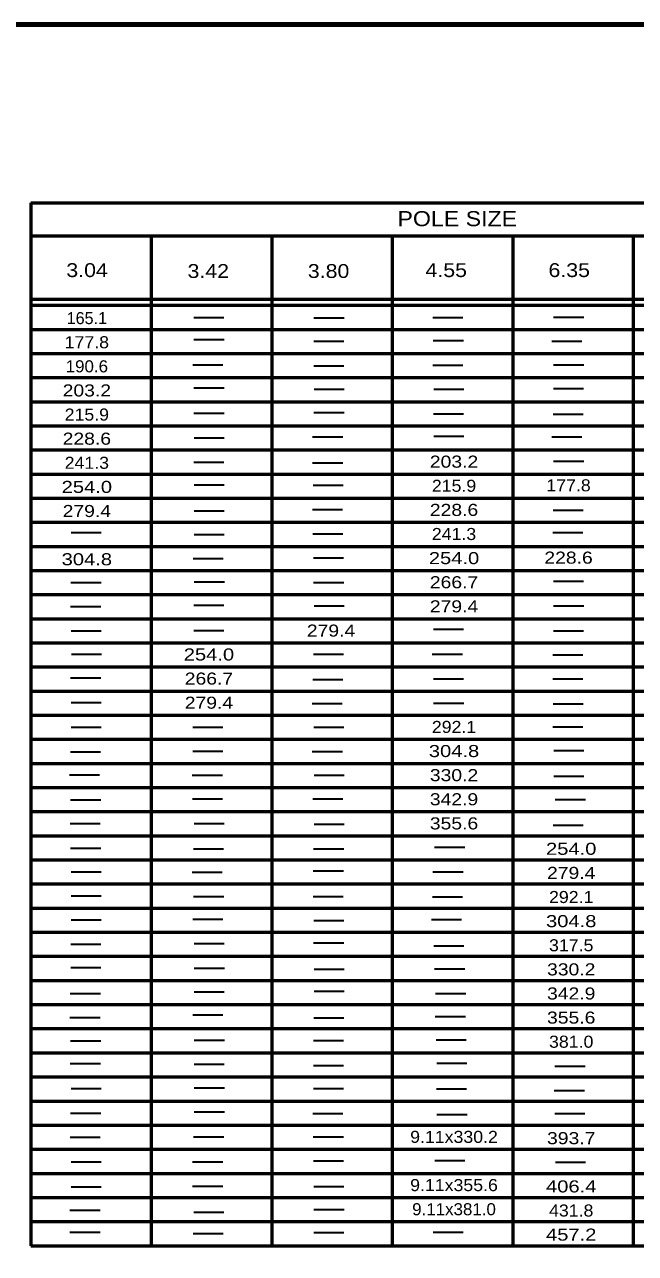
# Model space of a CAD drawing. Extents: x -711 to 145, y 25 to 569.
# Drawn here: x -252.6 to -112, y 280.2 to 562.7 of the extents above; entities that cross this region are included whole.
import ezdxf
from ezdxf.enums import TextEntityAlignment as Align

# ---------------------------------------------------------------- set-up
doc = ezdxf.new("R2010")
doc.units = 0
doc.header["$LTSCALE"] = 1.1
doc.layers.add('1', color=7, linetype='Continuous', lineweight=53)

msp = doc.modelspace()

# ---------------------------------------------------------------- linework, layer by layer
at = {"layer": '1'}
for p, q in [((-251.147, 521.717), (-251.147, 281.939)), ((-251.147, 521.717), (-44.796, 521.717)), ((-251.147, 514.094), (-57.107, 514.094)), ((-223.427, 514.094), (-223.427, 281.939)), ((-195.707, 514.094), (-195.707, 281.939)), ((-167.987, 514.094), (-167.987, 513.999)), ((-167.987, 514.094), (-167.987, 281.939)), ((-140.267, 514.094), (-140.267, 281.939)), ((-112.547, 514.094), (-112.547, 513.999)), ((-112.547, 514.094), (-112.547, 281.939)), ((-251.147, 499.541), (109.194, 499.541)), ((-251.147, 498.155), (109.194, 498.155)), ((-251.147, 492.611), (109.194, 492.611)), ((-251.147, 487.067), (109.194, 487.067)), ((-251.147, 481.523), (109.194, 481.523)), ((-251.147, 475.979), (109.194, 475.979)), ((-251.147, 470.435), (109.194, 470.435)), ((-251.147, 464.891), (109.194, 464.891)), ((-251.147, 459.347), (109.194, 459.347)), ((-251.147, 453.803), (109.194, 453.803)), ((-251.147, 448.259), (109.194, 448.259)), ((-251.147, 442.715), (109.194, 442.715)), ((-251.147, 437.171), (109.194, 437.171)), ((-251.147, 431.627), (109.194, 431.627)), ((-251.147, 426.083), (109.194, 426.083)), ((-251.147, 420.539), (109.194, 420.539)), ((-251.147, 414.995), (109.194, 414.995)), ((-251.147, 409.451), (109.194, 409.451)), ((-251.147, 403.907), (109.194, 403.907)), ((-251.147, 398.363), (109.194, 398.363)), ((-251.147, 392.819), (109.194, 392.819)), ((-251.147, 387.275), (109.194, 387.275)), ((-251.147, 381.731), (109.194, 381.731)), ((-251.147, 376.187), (109.194, 376.187)), ((-251.147, 370.643), (109.194, 370.643)), ((-251.147, 365.099), (109.194, 365.099)), ((-251.147, 359.555), (109.194, 359.555)), ((-251.147, 354.011), (109.194, 354.011)), ((-251.147, 348.467), (109.194, 348.467)), ((-251.147, 342.923), (109.194, 342.923)), ((-251.147, 337.379), (109.194, 337.379)), ((-251.147, 331.835), (109.194, 331.835)), ((-251.147, 326.291), (109.194, 326.291)), ((-251.147, 320.747), (109.194, 320.747)), ((-251.147, 315.203), (109.194, 315.203)), ((-251.147, 309.659), (109.194, 309.659)), ((-251.147, 304.115), (109.194, 304.115)), ((-251.147, 298.571), (109.194, 298.571)), ((-251.147, 293.027), (109.194, 293.027)), ((-251.147, 287.483), (109.194, 287.483)), ((-251.147, 281.939), (109.213, 281.939))]:
    msp.add_line(p, q, dxfattribs=at)
at = {"layer": '1', "lineweight": 35}
for p, q in [((-213.641, 495.341), (-206.71, 495.341)), ((-185.997, 495.27), (-179.067, 495.27)), ((-158.633, 495.341), (-151.703, 495.341)), ((-130.847, 495.413), (-123.917, 495.413)), ((-213.607, 490.263), (-206.677, 490.263)), ((-186.035, 489.91), (-179.105, 489.91)), ((-158.527, 490.015), (-151.597, 490.015)), ((-131.268, 489.913), (-124.338, 489.913)), ((-213.855, 484.444), (-206.925, 484.444)), ((-186.035, 484.234), (-179.105, 484.234)), ((-158.633, 484.339), (-151.703, 484.339)), ((-130.847, 484.482), (-123.917, 484.482)), ((-213.607, 479.156), (-206.677, 479.156)), ((-185.964, 478.874), (-179.034, 478.874)), ((-158.422, 478.874), (-151.492, 478.874)), ((-130.88, 478.979), (-123.95, 478.979)), ((-213.607, 473.337), (-206.677, 473.337)), ((-185.997, 473.514), (-179.067, 473.514)), ((-158.493, 473.16), (-151.563, 473.16)), ((-130.986, 473.126), (-124.056, 473.126)), ((-213.573, 467.695), (-206.643, 467.695)), ((-186.313, 467.871), (-179.383, 467.871)), ((-158.422, 468.082), (-151.492, 468.082)), ((-131.268, 467.871), (-124.338, 467.871)), ((-213.644, 462.052), (-206.714, 462.052)), ((-186.313, 461.947), (-179.383, 461.947)), ((-130.843, 462.334), (-123.913, 462.334)), ((-213.573, 456.869), (-206.643, 456.869)), ((-186.208, 456.764), (-179.278, 456.764)), ((-213.573, 450.873), (-206.643, 450.873)), ((-186.351, 451.193), (-179.421, 451.193)), ((-130.982, 451.05), (-124.052, 451.05)), ((-241.886, 445.867), (-234.956, 445.867)), ((-213.573, 445.408), (-206.643, 445.408)), ((-186.28, 445.585), (-179.35, 445.585)), ((-131.053, 445.867), (-124.123, 445.867)), ((-213.784, 439.942), (-206.853, 439.942)), ((-186.103, 440.048), (-179.173, 440.048)), ((-241.923, 434.406), (-234.993, 434.406)), ((-213.535, 434.582), (-206.605, 434.582)), ((-186.069, 434.439), (-179.139, 434.439)), ((-130.877, 434.688), (-123.947, 434.688)), ((-241.994, 428.869), (-235.064, 428.869)), ((-213.644, 429.222), (-206.714, 429.222)), ((-185.963, 429.046), (-179.033, 429.046)), ((-130.843, 429.046), (-123.913, 429.046)), ((-241.855, 423.332), (-234.925, 423.332)), ((-213.644, 423.403), (-206.714, 423.403)), ((-158.49, 423.685), (-151.56, 423.685)), ((-130.88, 423.332), (-123.95, 423.332)), ((-241.784, 417.904), (-234.854, 417.904)), ((-186.103, 417.938), (-179.173, 417.938)), ((-158.772, 417.904), (-151.842, 417.904)), ((-131.057, 417.761), (-124.127, 417.761)), ((-241.994, 412.472), (-235.064, 412.472)), ((-186.242, 412.119), (-179.312, 412.119)), ((-158.49, 412.224), (-151.56, 412.224)), ((-131.057, 412.296), (-124.127, 412.296)), ((-241.889, 406.83), (-234.959, 406.83)), ((-186.419, 406.582), (-179.489, 406.582)), ((-158.456, 406.687), (-151.526, 406.687)), ((-130.952, 406.477), (-124.022, 406.477)), ((-131.057, 401.222), (-124.127, 401.222)), ((-241.889, 401.117), (-234.959, 401.117)), ((-213.855, 401.117), (-206.925, 401.117)), ((-186.031, 401.117), (-179.101, 401.117)), ((-213.892, 395.651), (-206.962, 395.651)), ((-186.385, 395.579), (-179.455, 395.579)), ((-130.809, 395.794), (-123.879, 395.794)), ((-242.032, 395.474), (-235.102, 395.474)), ((-242.28, 390.186), (-235.35, 390.186)), ((-213.998, 390.114), (-207.068, 390.114)), ((-185.96, 390.08), (-179.03, 390.08)), ((-130.811, 389.853), (-123.881, 389.853)), ((-241.998, 384.472), (-235.068, 384.472)), ((-213.93, 384.649), (-207, 384.649)), ((-186.246, 384.649), (-179.316, 384.649)), ((-130.459, 384.528), (-123.529, 384.528)), ((-242.103, 379.006), (-235.173, 379.006)), ((-213.576, 379.007), (-206.646, 379.007)), ((-185.963, 378.864), (-179.033, 378.864)), ((-130.984, 378.599), (-124.054, 378.599)), ((-241.998, 373.364), (-235.068, 373.364)), ((-213.719, 373.188), (-206.789, 373.188)), ((-186.069, 373.188), (-179.139, 373.188)), ((-158.24, 373.575), (-151.31, 373.575)), ((-241.893, 367.899), (-234.963, 367.899)), ((-214.035, 367.794), (-207.105, 367.794)), ((-186.14, 368.147), (-179.21, 368.147)), ((-158.624, 367.903), (-151.694, 367.903)), ((-241.855, 362.396), (-234.925, 362.396)), ((-213.682, 362.253), (-206.752, 362.253)), ((-186.212, 362.257), (-179.282, 362.257)), ((-158.729, 362.116), (-151.799, 362.116)), ((-241.855, 356.825), (-234.925, 356.825)), ((-213.858, 357.002), (-206.928, 357.002)), ((-186.035, 356.682), (-179.105, 356.682)), ((-158.979, 356.894), (-152.049, 356.894)), ((-241.961, 351.288), (-235.031, 351.288)), ((-213.576, 351.394), (-206.646, 351.394)), ((-186.069, 351.571), (-179.139, 351.571)), ((-158.413, 350.904), (-151.483, 350.904)), ((-241.961, 345.928), (-235.031, 345.928)), ((-213.543, 345.718), (-206.613, 345.718)), ((-185.963, 345.541), (-179.033, 345.541)), ((-158.236, 345.578), (-151.306, 345.578)), ((-242.066, 339.899), (-235.136, 339.899)), ((-213.577, 340.286), (-206.647, 340.286)), ((-185.963, 340.463), (-179.033, 340.463)), ((-157.991, 339.948), (-151.061, 339.948)), ((-242.137, 334.396), (-235.207, 334.396)), ((-213.862, 334.997), (-206.932, 334.997)), ((-186.035, 334.362), (-179.105, 334.362)), ((-158.064, 334.625), (-151.134, 334.625)), ((-241.994, 329.002), (-235.064, 329.002)), ((-213.543, 329.178), (-206.613, 329.178)), ((-186.103, 329.107), (-179.173, 329.107)), ((-157.889, 329.3), (-150.96, 329.3)), ((-242.066, 323.856), (-235.136, 323.856)), ((-213.573, 323.641), (-206.643, 323.641)), ((-186.103, 323.393), (-179.173, 323.393)), ((-157.715, 323.895), (-150.785, 323.895)), ((-130.527, 323.228), (-123.597, 323.228)), ((-241.889, 318.071), (-234.959, 318.071)), ((-213.535, 318.248), (-206.605, 318.248)), ((-186.103, 318.071), (-179.173, 318.071)), ((-157.82, 318.006), (-150.89, 318.006)), ((-130.705, 317.586), (-123.775, 317.586)), ((-241.995, 312.429), (-235.065, 312.429)), ((-213.535, 312.711), (-206.605, 312.711)), ((-186.28, 312.357), (-179.35, 312.357)), ((-157.679, 312.119), (-150.749, 312.119)), ((-130.564, 312.365), (-123.634, 312.365)), ((-242.1, 306.892), (-235.17, 306.892)), ((-213.674, 306.963), (-206.744, 306.963)), ((-186.137, 306.963), (-179.207, 306.963)), ((-241.889, 301.249), (-234.959, 301.249)), ((-213.923, 301.249), (-206.993, 301.249)), ((-186.103, 301.426), (-179.173, 301.426)), ((-158.175, 301.503), (-151.245, 301.503)), ((-130.412, 301.175), (-123.482, 301.175)), ((-241.889, 295.464), (-234.959, 295.464)), ((-213.923, 295.607), (-206.993, 295.607)), ((-186.031, 295.536), (-179.101, 295.536)), ((-242.137, 290.142), (-235.207, 290.142)), ((-213.64, 289.683), (-206.71, 289.683)), ((-185.997, 290.247), (-179.067, 290.247)), ((-242.137, 285.064), (-235.207, 285.064)), ((-213.783, 284.71), (-206.853, 284.71)), ((-186.031, 284.959), (-179.101, 284.959)), ((-158.588, 285.04), (-151.658, 285.04))]:
    msp.add_line(p, q, dxfattribs=at)
at = {"layer": '1', "lineweight": 158}
msp.add_lwpolyline([(138.105, 562.675), (-653.595, 562.575), (-653.495, 36.575)], dxfattribs=at)

# ---------------------------------------------------------------- texts
at = {"layer": '1', "width": 1.15}
for s, height, p in [('POLE SIZE', 3.465, (-166.776, 516.324)), ('3.04', 3.188, (-242.97, 504.627)), ('3.42', 3.188, (-215.079, 504.422)), ('3.80', 3.188, (-187.394, 504.422)), ('4.55', 3.188, (-160.324, 504.627)), ('6.35', 3.188, (-132.023, 504.627))]:
    msp.add_text(s, height=height, dxfattribs=at).set_placement(p)
at = {"layer": '1'}
msp.add_text('165.1', height=2.772, dxfattribs=at).set_placement((-238.253, 493.808), align=Align.CENTER)
for s, width, p in [('177.8', 1.1, (-238.253, 488.264)), ('190.6', 1.05, (-238.253, 482.72)), ('203.2', 1.2, (-238.253, 477.176)), ('215.9', 1.1, (-238.253, 471.632)), ('228.6', 1.2, (-238.253, 466.088)), ('241.3', 1.1, (-238.253, 460.544)), ('203.2', 1.2, (-153.762, 460.804)), ('254.0', 1.25, (-238.253, 455)), ('215.9', 1.1, (-153.762, 455.26)), ('177.8', 1.1, (-127.41, 455.368)), ('279.4', 1.2, (-238.253, 449.456)), ('228.6', 1.2, (-153.763, 449.716)), ('241.3', 1.1, (-153.763, 444.172)), ('304.8', 1.25, (-238.253, 438.368)), ('254.0', 1.25, (-153.762, 438.628)), ('228.6', 1.2, (-127.41, 438.736)), ('266.7', 1.2, (-153.762, 433.084)), ('279.4', 1.2, (-153.762, 427.54)), ('279.4', 1.2, (-182.062, 421.964)), ('254.0', 1.25, (-210.157, 416.475)), ('266.7', 1.2, (-210.157, 410.931)), ('279.4', 1.2, (-210.157, 405.387)), ('292.1', 1.1, (-153.762, 399.82)), ('304.8', 1.25, (-153.762, 394.276)), ('330.2', 1.2, (-153.762, 388.732)), ('342.9', 1.2, (-153.762, 383.188)), ('355.6', 1.2, (-153.763, 377.644)), ('254.0', 1.25, (-126.795, 371.803)), ('279.4', 1.2, (-126.795, 366.259)), ('292.1', 1.1, (-126.795, 360.715)), ('304.8', 1.25, (-126.795, 355.171)), ('317.5', 1.1, (-126.795, 349.627)), ('330.2', 1.2, (-126.795, 344.083)), ('342.9', 1.2, (-126.795, 338.539)), ('355.6', 1.2, (-126.795, 332.995)), ('381.0', 1.1, (-126.795, 327.451)), ('9.11x330.2', 1.1, (-153.762, 305.572)), ('393.7', 1.2, (-126.795, 305.275)), ('9.11x355.6', 1.1, (-153.762, 294.484)), ('406.4', 1.25, (-126.795, 294.187)), ('9.11x381.0', 1.05, (-153.762, 288.94)), ('431.8', 1.1, (-126.795, 288.643)), ('457.2', 1.25, (-126.795, 283.099))]:
    msp.add_text(s, height=2.772, dxfattribs=dict(at, width=width)).set_placement(p, align=Align.CENTER)

doc.saveas('drawing.dxf')
